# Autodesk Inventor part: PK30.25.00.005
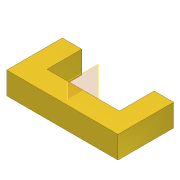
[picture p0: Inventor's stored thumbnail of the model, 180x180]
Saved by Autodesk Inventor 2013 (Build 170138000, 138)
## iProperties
Created: 2006-03
Part Number: PK30.25.00.005
Material: Steel, Mild
Document SubType Name: Modeling
Designer: SAlex
Manufacturer: Standard
Standards Organization: Custom
Density: 7.86 g/cm^3
Author: SAlex
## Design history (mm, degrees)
sketch "Эскиз1"
  geometry: L1 (0, 0)-(0, -40); L2 (0, -40)-(80, -40); L3 (80, -40)-(80, 0); L4 (80, 0)-(66, 0); L5 (66, 0)-(66, -25); L6 (66, -25)-(14, -25); L7 (14, -25)-(14, 0); L8 (14, 0)-(0, 0)
  constraints: 16 end point, 6 parallel, 2 collinear, 1 perpendicular, 1 vertical, 1 other
  dimensions: "d0" = 80 distance of L1.end L2.end; "d1" = 40 distance of L1.start L1.end; "d2" = 25 distance of L6.end L7.end; "d3" = 52 distance between parallel lines of L5 L7
extrude "Выдавливание1" new body sketch "Эскиз1" distance "d4" = 16; taper "d5" = 0 deg
workplane "Work Plane1"
body "Solid1"
